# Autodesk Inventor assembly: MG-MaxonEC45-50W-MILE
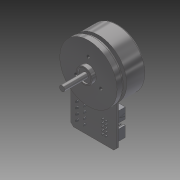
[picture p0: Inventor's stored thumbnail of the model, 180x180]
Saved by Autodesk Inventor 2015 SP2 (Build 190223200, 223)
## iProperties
Created: 2015-08
Part Number: MG-MaxonEC45-50W-MILE
Document SubType Name: Assembly
Designer: ryll
Author: ryll
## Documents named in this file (4)
- D:\Tigers SVN\mechanik\2016\Inventor\Kaufteile\MG-MaxonEC45-50W-MILE.iam
- D:\Tigers SVN\mechanik\2016\Inventor\Kaufteile\MaxonEC45-50W-MILE.ipt
- D:\Tigers SVN\mechanik\2016\Inventor\Kaufteile\IDC Stecker 10pol.ipt
- D:\Tigers SVN\mechanik\2016\Inventor\Kaufteile\Molex MiniFit 8pol.ipt
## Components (3 placed, 3 different names)
1. MaxonEC45-50W-MILE:1 — Passend:1, Passend:2, Fluchtend:1, Fluchtend:2, Fluchtend:3, Fluchtend:4
2. IDC Stecker 10pol:1 — Passend:2, Fluchtend:1, Fluchtend:2
3. Molex MiniFit 8pol:1 — Passend:1, Fluchtend:3, Fluchtend:4
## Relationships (6: Flush 4, Mate 2)
- Passend:1 [Mate]: MaxonEC45-50W-MILE:1 ↔ Molex MiniFit 8pol:1
- Passend:2 [Mate]: MaxonEC45-50W-MILE:1 ↔ IDC Stecker 10pol:1
- Fluchtend:1 [Flush]: MaxonEC45-50W-MILE:1 ↔ IDC Stecker 10pol:1
- Fluchtend:2 [Flush]: MaxonEC45-50W-MILE:1 ↔ IDC Stecker 10pol:1
- Fluchtend:3 [Flush]: MaxonEC45-50W-MILE:1 ↔ Molex MiniFit 8pol:1
- Fluchtend:4 [Flush]: MaxonEC45-50W-MILE:1 ↔ Molex MiniFit 8pol:1
